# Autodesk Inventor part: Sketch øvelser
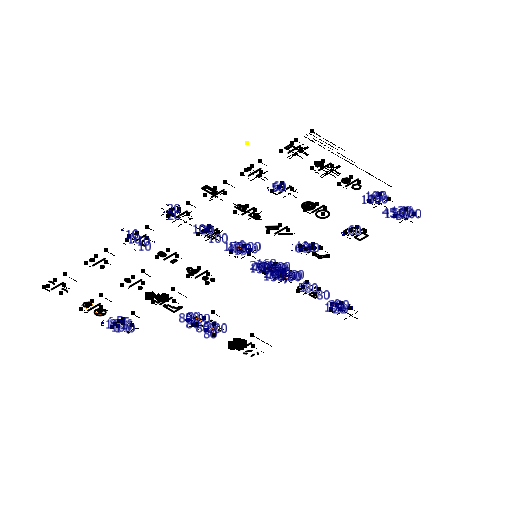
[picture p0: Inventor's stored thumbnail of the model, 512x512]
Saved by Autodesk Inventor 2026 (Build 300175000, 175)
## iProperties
Created: 2013-10
Part Number: Sketch øvelser
Material: Generic
Document SubType Name: Modeling
Designer: Cadskolen
Density: 1 g/cm^3
Appearance: Default
Author: Cadskolen
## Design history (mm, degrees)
sketch "Sketch1" dims "d84" = 160, "d93" = 160
  geometry: L1 (595.264, 365.334)-(645.374, 365.334); L2 (645.374, 365.334)-(645.374, 482.695); L3 (645.374, 482.695)-(595.264, 482.695); L4 (595.264, 482.695)-(595.264, 365.334); L5 (635.502, 482.695)-(635.502, 516.102); L6 (635.502, 516.102)-(605.136, 516.102); L7 (605.136, 516.102)-(605.136, 482.695); L8 (617.796, 503.263)-(611.115, 503.263); L9 (611.115, 503.263)-(611.115, 496.582); L10 (611.115, 496.582)-(617.796, 496.582); L11 (617.796, 496.582)-(617.796, 503.263); L12 (629.524, 503.263)-(629.524, 496.582); L13 (629.524, 496.582)-(622.843, 496.582); L14 (622.843, 503.263)-(629.524, 503.263); L15 (622.843, 496.582)-(622.843, 503.263); L16 (743.982, 612.24)-(743.982, 296.408); L17 (1519.692, 612.24)-(1519.692, 296.408); L18 (1375.676, 365.334)-(1375.676, 435.476); L19 (1375.676, 503.263)-(1422.899, 503.263); L20 (1422.899, 365.334)-(1422.899, 435.476); L21 (1375.676, 365.334)-(1422.899, 365.334); L22 (1519.692, -400.449)-(1519.692, -716.281); L23 (743.982, -400.449)-(743.982, -716.281); L24 (621.757, -543.115)-(621.757, -615.071); L25 (567.899, -615.071)-(567.899, -543.115); L26 (907.768, -543.115)-(907.768, -615.071); L27 (853.91, -615.071)-(853.91, -543.115); L28 (2216.427, 612.24)-(2216.427, 296.408); L29 (2174.046, 418.72)-(2134.058, 349.459); L30 (2134.058, 487.98)-(2174.046, 418.72); L31 (2154.052, 384.089)-(2094.07, 487.98); L32 (2034.089, 384.089)-(2154.052, 453.35); L33 (2154.052, 384.089)-(2029.464, 445.34); L34 (2154.052, 453.35)-(2029.464, 445.34); L35 (2054.083, 487.98)-(2134.058, 487.98); L36 (2054.083, 349.459)-(2014.095, 418.72); L37 (2094.07, 487.98)-(2034.089, 384.089); L38 (2014.095, 418.72)-(2054.083, 487.98); L39 (2134.058, 349.459)-(2054.083, 349.459); L40 (2401.715, 349.459)-(2321.74, 349.459); L41 (2321.74, 349.459)-(2281.752, 418.72); L42 (2281.752, 418.72)-(2321.74, 487.98); L43 (2321.74, 487.98)-(2401.715, 487.98); L44 (2401.715, 487.98)-(2441.703, 418.72); L45 (2441.703, 418.72)-(2401.715, 349.459); L46 (2968.737, 612.24)-(2968.737, 296.408); L47 (2773.644, 349.459)-(2873.644, 349.459); L48 (2873.644, 349.459)-(2873.644, 499.459); L49 (2873.644, 499.459)-(2833.644, 499.459); L50 (2833.644, 499.459)-(2833.644, 399.459); L51 (2833.644, 399.459)-(2773.644, 349.459); L52 (3627.748, 612.24)-(3627.748, 296.408); L53 (3459.271, 352.872)-(3494.626, 388.228); L54 (3459.271, 352.872)-(3509.271, 352.872); L55 (3494.626, 388.228)-(3494.626, 508.228); L56 (3494.626, 508.228)-(3554.626, 508.228); L57 (3554.626, 508.228)-(3554.626, 388.228); L58 (3554.626, 388.228)-(3589.982, 352.872); L59 (3589.982, 352.872)-(3459.271, 352.872); L60 (2361.766, -400.449)-(2361.766, -716.281); L61 (2094.07, -579.093)-(2130.048, -543.115); L62 (2130.048, -543.115)-(2163.143, -603.12); L63 (2249.145, -551.499)-(2264.383, -579.129); L64 (2198.104, -615.683)-(2249.145, -551.499)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; C1 r 60 at (1382.221, -584.713); C2 r 117.468 at (2174.046, -615.071); C3 r 12.62 at (2247.238, -574.173); C4 r 17.397 at (2125.989, -571.777); C5 r 117.468 at (2534.836, -615.071); C6 r 30 at (3250.678, -616.233); C7 r 8.77 at (3091.416, -1597.549); C8 r 8.77 at (3154.256, -1467.183); C9 r 8.77 at (2947.588, -1597.549); C10 r 8.77 at (3308.701, -1597.661); C11 r 8.77 at (3515.672, -1468.424); C12 r 8.77 at (3452.612, -1597.661); C13 r 10 at (2229.444, -2443.182); C14 r 100 at (3064.902, -2483.051); C15 r 100 at (3418.128, -2483.051); C16 r 10 at (4633.839, -2483.051); C17 r 10 at (4733.839, -2444.854); C18 r 10 at (4833.839, -2483.051); C19 r 45.196 at (2056.577, -3524.495); C20 r 32.218 at (2180.263, -3464.495); C21 r 25.601 at (2180.263, -3596.973); C22 r 32.218 at (2579.099, -3464.495); C23 r 45.196 at (2455.413, -3524.495); C24 r 25.601 at (2579.099, -3596.973); C25 r 28.41 at (888.17, -4576.218); C26 r 12.176 at (1514.696, -4562.014); C27 r 25.487 at (1514.696, -4562.014); C28 r 12.176 at (1839.929, -4562.014); C29 r 25.487 at (1839.929, -4562.014); C30 r 25 at (1382.221, -584.713); C31 r 71.786 at (1540.183, -5614.422); C32 r 71.786 at (1865.416, -5614.422); A1 r 98.249 centre (1473.925, 435.476) between (1385.556, 478.417) and (1375.676, 435.476); A2 r 18.103 centre (1369.274, 486.329) between (1385.556, 478.417) and (1375.676, 503.263); A3 r 18.103 centre (1429.301, 486.329) between (1422.899, 503.263) and (1413.018, 478.417); A4 r 98.249 centre (1324.65, 435.476) between (1422.899, 435.476) and (1413.018, 478.417); A5 r 20.013 centre (3154.256, -1467.183) between (3172.284, -1475.873) and (3136.229, -1458.493); A6 r 20.014 centre (3091.416, -1597.549) between (3073.387, -1588.859) and (3109.359, -1606.415); A7 r 20.014 centre (2947.588, -1597.549) between (2947.588, -1577.535) and (2947.588, -1617.563); A8 r 20 centre (3308.701, -1597.661) between (3308.701, -1577.661) and (3308.701, -1617.661); A9 r 20 centre (3515.672, -1468.424) between (3533.647, -1477.194) and (3497.698, -1459.653); A10 r 20 centre (3452.612, -1597.661) between (3434.638, -1588.891) and (3470.587, -1606.432); A11 r 20 centre (512.514, -2535.732) between (492.514, -2535.732) and (532.514, -2535.732); A12 r 20 centre (512.514, -2535.732) between (512.514, -2515.732) and (512.514, -2555.732); A13 r 20 centre (512.514, -2396.97) between (532.514, -2396.97) and (492.514, -2396.97); A14 r 20 centre (668.163, -2535.732) between (668.163, -2555.732) and (668.163, -2515.732); A15 r 20 centre (1412.155, -2501.334) between (1392.155, -2501.334) and (1432.155, -2501.334); A16 r 20 centre (1412.155, -2441.334) between (1432.155, -2441.334) and (1392.155, -2441.334); A17 r 10 centre (2158.733, -2513.892) between (2151.662, -2506.821) and (2165.804, -2520.963); A18 r 10 centre (2300.155, -2372.471) between (2307.226, -2379.542) and (2293.084, -2365.4); A19 r 10 centre (2300.155, -2513.892) between (2293.084, -2520.963) and (2307.226, -2506.821); A20 r 10 centre (2158.733, -2372.471) between (2165.804, -2365.4) and (2151.662, -2379.542); A21 r 80 centre (3064.902, -2483.051) between (3064.902, -2403.051) and (3011.526, -2423.46); A22 r 80 centre (3064.902, -2483.051) between (3104.902, -2413.768) and (3024.902, -2413.768); A23 r 88 centre (3064.902, -2483.051) between (3108.902, -2406.84) and (3020.902, -2406.84); A24 r 72 centre (3064.902, -2483.051) between (3100.902, -2420.697) and (3028.902, -2420.697); A25 r 8 centre (3104.902, -2413.768) between (3100.902, -2420.697) and (3108.902, -2406.84); A26 r 8 centre (3024.902, -2413.768) between (3020.902, -2406.84) and (3028.902, -2420.697); A27 r 80 centre (3064.902, -2483.051) between (2995.62, -2523.051) and (3134.184, -2523.051); A28 r 88 centre (3064.902, -2483.051) between (2988.692, -2527.051) and (3141.113, -2527.051); A29 r 72 centre (3064.902, -2483.051) between (3002.548, -2519.051) and (3127.256, -2519.051); A30 r 8 centre (2995.62, -2523.051) between (3002.548, -2519.051) and (2988.692, -2527.051); A31 r 8 centre (3134.184, -2523.051) between (3141.113, -2527.051) and (3127.256, -2519.051); A32 r 80 centre (3418.128, -2483.051) between (3458.128, -2413.768) and (3378.128, -2413.768); A33 r 80 centre (3418.128, -2483.051) between (3418.128, -2403.051) and (3364.752, -2423.46); A34 r 80 centre (3418.128, -2483.051) between (3348.846, -2523.051) and (3487.41, -2523.051); A35 r 80 centre (3903.482, -2475.051) between (3983.482, -2475.051) and (3903.482, -2395.051); A36 r 50 centre (3903.482, -2475.051) between (3953.482, -2475.051) and (3903.482, -2425.051); A37 r 58 centre (3903.482, -2475.051) between (3961.482, -2475.051) and (3903.482, -2417.051); A38 r 42 centre (3903.482, -2475.051) between (3945.482, -2475.051) and (3903.482, -2433.051); A39 r 8 centre (3953.482, -2475.051) between (3945.482, -2475.051) and (3961.482, -2475.051); A40 r 8 centre (3903.482, -2425.051) between (3903.482, -2417.051) and (3903.482, -2433.051); A41 r 80 centre (4205.51, -2475.051) between (4285.51, -2475.051) and (4205.51, -2395.051); A42 r 150 centre (4733.839, -2594.854) between (4833.839, -2483.051) and (4633.839, -2483.051); A43 r 170 centre (4733.839, -2594.854) between (4847.173, -2468.143) and (4620.506, -2468.143); A44 r 130 centre (4733.839, -2594.854) between (4820.506, -2497.958) and (4647.173, -2497.958); A45 r 20 centre (4833.839, -2483.051) between (4820.506, -2497.958) and (4847.173, -2468.143); A46 r 20 centre (4633.839, -2483.051) between (4620.506, -2468.143) and (4647.173, -2497.958); A47 r 110 centre (556.1, -3568.34) between (666.1, -3568.34) and (556.1, -3458.34); A48 r 50.13 centre (1399.273, -3546.843) between (1399.273, -3596.973) and (1399.273, -3496.713); A49 r 50.13 centre (1350.35, -3546.843) between (1350.35, -3496.713) and (1350.35, -3596.973); A50 r 79.667 centre (2136, -3530.734) between (2056.577, -3524.495) and (2180.263, -3464.495); A51 r 40 centre (3373.786, -4662.886) between (3341.949, -4638.669) and (3362.172, -4624.609); A52 r 40 centre (3164.008, -4664.567) between (3194.492, -4638.669) and (3162.172, -4624.609); A53 r 40 centre (3602.728, -4664.567) between (3633.213, -4638.669) and (3600.893, -4624.609); A54 r 40 centre (3812.506, -4662.886) between (3780.67, -4638.669) and (3800.893, -4624.609); A55 r 128.302 centre (606.855, -5693.319) between (670.825, -5582.102) and (536.175, -5586.241); A56 r 128.302 centre (937.538, -5693.319) between (1001.508, -5582.102) and (866.858, -5586.241); A57 r 99.722 centre (1540.183, -5614.422) between (1639.905, -5614.422) and (1440.461, -5614.422); A58 r 99.722 centre (1865.416, -5614.422) between (1965.139, -5614.422) and (1765.694, -5614.422); A59 r 8 centre (2311.363, -5687.637) between (2303.363, -5687.637) and (2311.363, -5695.637); A60 r 8 centre (2400.15, -5687.637) between (2400.15, -5695.637) and (2408.15, -5687.637); A61 r 16 centre (2309.363, -5689.637) between (2293.363, -5689.637) and (2309.363, -5705.637); A62 r 16 centre (2402.15, -5689.637) between (2402.15, -5705.637) and (2418.15, -5689.637); 175 further points; 1 other entity
  constraints: 733 end point, 136 point on circle, 118 parallel, 94 centre point, 86 perpendicular, 74 tangent, 45 coincident, 40 point on line, 34 midpoint, 30 horizontal alignment, 22 horizontal, 10 collinear, 6 equal radius, 5 vertical alignment, 4 symmetric about line, 3 vertical, 2 equal length, 183 other
  dimensions: "d5" = 60 radius of C1; "d8" = 150 distance of L47.end L48.end; "d9" = 40 distance of L48.end L49.end; "d10" = 100 distance of L49.end L50.end; "d19" = 50 distance of L53.start L53.end; "d20" = 45 deg angle of L54 L53; "d21" = 120 distance of L53.end L55.end; "d22" = 60 distance of L55.end L56.end; "d23" = 50 distance of L57.end L58.end; "d24" = 135 deg angle of L58 L57; "d43" = 60 distance of L175.start L175.end; "d44" = 10 distance of L175.end L176.end; "d45" = 80 distance of L181.start L181.end; "d46" = 10 distance of L181.end L182.end; "d55" = 20 radius of A13; "d56" = 20 radius of A14; "d59" = 100 distance between parallel lines of L208 L207; "d60" = 100 distance between parallel lines of L216 L210; "d61" = 20 radius of A16; "d67" = 100 distance of point (2229.444, -2443.182) L223.end; "d68" = 10 radius of A18; "d69" = 100 distance of point (2229.444, -2443.182) L226.end; "d70" = 10 radius of A20; "d71" = 10 radius of C13; "d83" = 200 diameter of C14; "d85" = 60 deg angle of L230 L231; "d86" = 120 deg angle of L232 L231; "d87" = 8 radius of A26; "d88" = 30 deg angle of L233 L231; "d90" = 150 deg angle of L234 L231; "d91" = 8 radius of A30; "d92" = 200 diameter of C15; "d94" = 60 deg angle of L236 L238; "d95" = 120 deg angle of L237 L238; "d97" = 30 deg angle of L239 L238; "d98" = 150 deg angle of L240 L238; "d114" = 80 radius of A35; "d115" = 50 radius of A36; "d116" = 8 radius of A40; "d117" = 80 radius of A41; "d124" = 200 distance of A42.end A42.start; "d125" = 150 radius of A42; "d126" = 20 radius of A45; "d127" = 10 radius of C16; "d128" = 10 radius of C17; "d129" = 10 radius of C18; "d140" = 10 distance of L253.start L255.end; "d141" = 10 distance between parallel lines of L254 L257; "d142" = 10 distance of L259.start L259.end; "d143" = 10 distance between parallel lines of L262 L263; "d153" = 200 distance of L311.end L310.end; "d155" = 50 distance between parallel lines of L314 L315; "d156" = 30 distance between parallel lines of L311 L314; "d157" = 80 diameter of A52; "d158" = 80 diameter of A51; "d159" = 200 distance of L318.start L324.start; "d160" = 50 distance between parallel lines of L323 L322; "d161" = 30 distance between parallel lines of L324 L323; "d162" = 80 diameter of A53; "d163" = 80 diameter of A54; "d164" = 50 diameter of C30; "d175" = 45 deg angle of L223 L337; "d176" = 135 deg angle of L226 L337; "d177" = 100 distance of L47.start L47.end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
